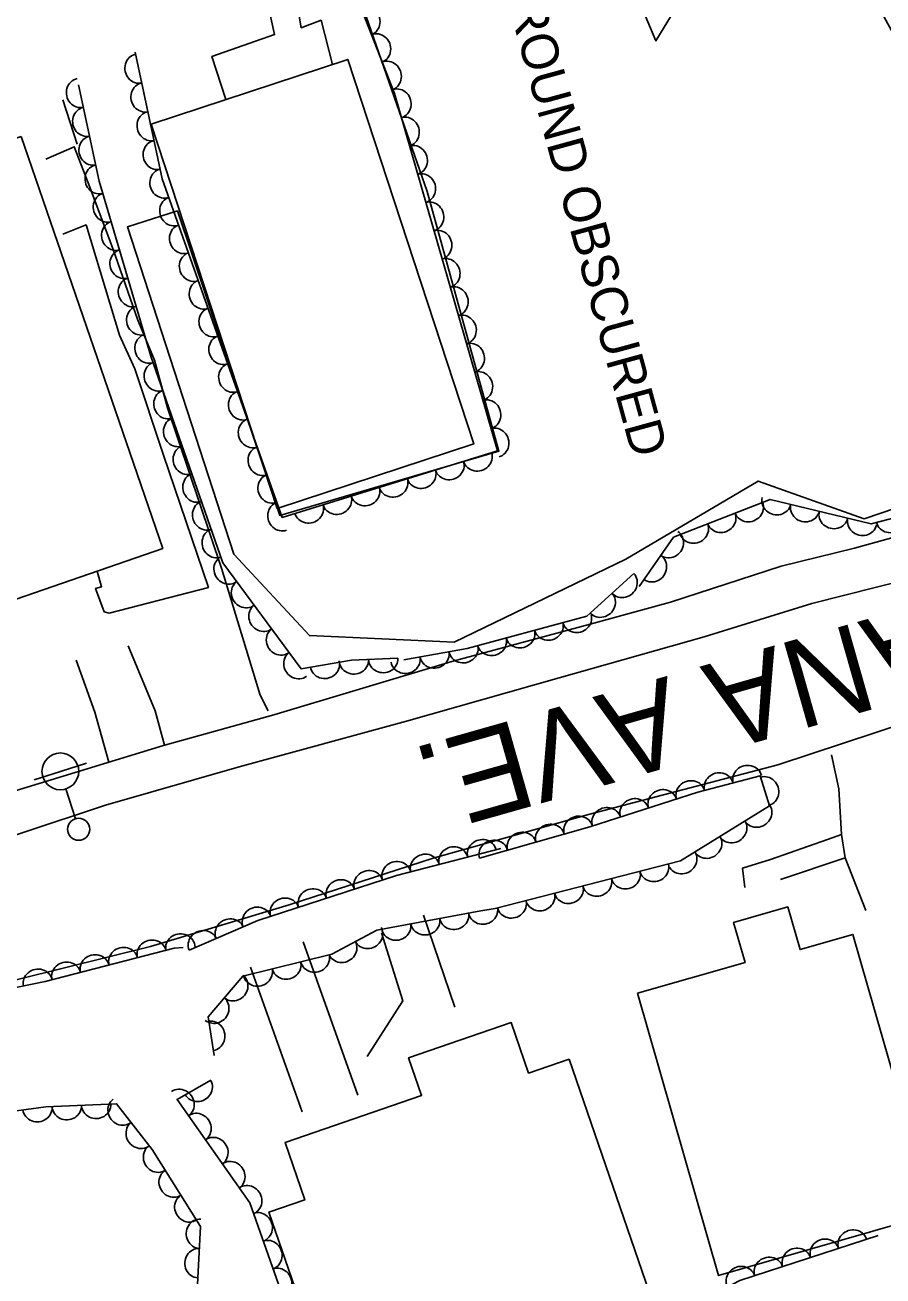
# Model space of a CAD drawing. Extents: x 1722896 to 1754269, y 648279 to 666297.
# Drawn here: x 1725232.8 to 1725349.5, y 665060.6 to 665230.7 of the extents above; entities that cross this region are included whole.
import ezdxf

# ---------------------------------------------------------------- set-up
doc = ezdxf.new("R2010")
doc.units = 0
for name, color, linetype in [('DESIGN - CENTERLINE - Proposed Text', 7, 'Continuous'), ('DESIGN - SHEET - Linework', 7, 'Continuous'), ('SURVEY - CENTERLINE - Preliminary', 7, 'Continuous'), ('SURVEY - CENTERLINE - Preliminary Text', 7, 'Continuous'), ('SURVEY - DTM - Breaklines', 7, 'Continuous'), ('SURVEY - VEGETATION - Features with Text', 7, 'Continuous')]:
    doc.layers.add(name, color=color, linetype=linetype)

msp = doc.modelspace()

# ---------------------------------------------------------------- linework, layer by layer
at = {"layer": 'DESIGN - CENTERLINE - Proposed Text'}
for points in [[(1725274.62, 665225.33), (1725273.06, 665231.34), (1725270.36, 665230.33), (1725269.07, 665237.77), (1725265.2, 665236.46), (1725266.72, 665229.4), (1725258.2, 665226.42), (1725260.12, 665220.57)], [(1725265.84, 665137.44), (1725264.75, 665139.58), (1725259.51, 665156.85), (1725252.15, 665178.66), (1725250.38, 665185.12), (1725248.14, 665190.57), (1725244.71, 665200.32), (1725241.39, 665209.23), (1725239.48, 665214.15), (1725235.62, 665212.47)], [(1725242.58, 665156.45), (1725243.2, 665154.31), (1725242.38, 665154.09), (1725243.57, 665150.91), (1725244.24, 665150.72), (1725257.73, 665154.23), (1725251.61, 665172.2), (1725247.7, 665183.94), (1725245.64, 665188.51), (1725241.08, 665203.52), (1725237.92, 665202.28)], [(1725245.64, 665157.48), (1725245.64, 665157.48)], [(1725330.68, 665113.43), (1725330.38, 665116.08), (1725334.17, 665117.24), (1725341.94, 665119.94), (1725343.84, 665120.62)], [(1725335.56, 665114.52), (1725344.35, 665117.47)], [(1725291.26, 665097.15), (1725286.97, 665109.66)], [(1725281.27, 665107.26), (1725284.18, 665098.02), (1725279.31, 665090.45)]]:
    msp.add_lwpolyline(points, dxfattribs=at)
for points in [[(1725249.93, 665217.23), (1725267.08, 665164.97), (1725293.83, 665173.75), (1725276.68, 665226.01)], [(1725232.24, 665215.53), (1725251.52, 665159.53), (1725224.05, 665150.07), (1725204.77, 665206.07)], [(1725316.1, 665099.05), (1725327.13, 665060.66), (1725356.32, 665069.05), (1725345.39, 665107.05), (1725338.2, 665104.99), (1725336.53, 665110.8), (1725329.16, 665108.68), (1725330.72, 665103.25)], [(1725306.79, 665090.09), (1725318.69, 665055.58), (1725275.79, 665040.8), (1725265.97, 665069.29), (1725270.84, 665070.96), (1725268.15, 665078.77), (1725286.72, 665085.17), (1725284.96, 665090.26), (1725298.92, 665095.07), (1725301.29, 665088.19)]]:
    msp.add_lwpolyline(points, close=True, dxfattribs=at)
at = {"layer": 'SURVEY - CENTERLINE - Preliminary'}
msp.add_lwpolyline([(1725301.17, 665269.92), (1725318.59, 665228.54), (1725330.19, 665247.6), (1725342.42, 665244.95), (1725356.56, 665219.19), (1725374.83, 665212.76), (1725380.19, 665187.77), (1725384.4, 665176.29), (1725346.92, 665163.57), (1725332.51, 665168.68), (1725314.53, 665158.06), (1725291.17, 665146.77), (1725271.47, 665147.68), (1725261.18, 665158.75), (1725246.72, 665203.25), (1725253.51, 665205.43), (1725267.43, 665164.03), (1725297.24, 665172.77), (1725287.5, 665208.06), (1725270.51, 665256.75), (1725301.17, 665269.92)], dxfattribs=at)
at = {"layer": 'SURVEY - CENTERLINE - Preliminary Text'}
for points in [[(1725519.42, 665223.67), (1725519.99, 665212.34), (1725515.67, 665197.19), (1725507.51, 665185.29), (1725492.83, 665177.77), (1725479.67, 665171.83), (1725461.36, 665165.41), (1725436.69, 665158.3), (1725416.91, 665154.11), (1725361.71, 665138.86), (1725335.17, 665130.12), (1725309.43, 665123.37), (1725288.3, 665117.43), (1725268.71, 665111.09), (1725249.84, 665105.41), (1725220, 665098.02), (1725197.01, 665091.34), (1725171.35, 665084.05), (1725152.36, 665078.27), (1725107.36, 665064.42), (1725081.37, 665056.76)], [(1725237.91, 665220.54), (1725239.88, 665214.51)], [(1725489.9, 665203.84), (1725487.04, 665201.88), (1725479.76, 665199.13), (1725463.22, 665193.38), (1725448.62, 665189.15), (1725429.03, 665183.37), (1725410.31, 665178.43), (1725386.01, 665171.28), (1725363.95, 665164.66), (1725345.61, 665159.57), (1725335.66, 665157.11), (1725320.58, 665152.24), (1725309.67, 665149.23), (1725290.83, 665144.14), (1725266.63, 665136.92), (1725251.62, 665132.76), (1725231.45, 665126.57)], [(1725488.25, 665195.87), (1725480.71, 665193.05), (1725469.88, 665189.35), (1725454.98, 665184.69), (1725439.96, 665180.41), (1725421.48, 665174.77), (1725402.66, 665169), (1725382, 665163.54), (1725357.22, 665156.45), (1725339.8, 665152.05), (1725325.18, 665147.53), (1725305.43, 665141.93), (1725284.68, 665136.03), (1725261.92, 665129.84), (1725243.74, 665124.63), (1725221.16, 665117.16)], [(1725251.77, 665132.8), (1725250.51, 665137.45), (1725246.8, 665146.28)], [(1725244.2, 665130.48), (1725242.27, 665137.29), (1725239.75, 665144.35)], [(1725342.47, 665131.47), (1725343.47, 665126.84), (1725343.84, 665120.62), (1725344.35, 665117.47), (1725347.15, 665110.29)], [(1725270.64, 665106.05), (1725278.07, 665085.2)], [(1725263.44, 665102.58), (1725270.5, 665082.92)]]:
    msp.add_lwpolyline(points, dxfattribs=at)
at = {"layer": 'SURVEY - DTM - Breaklines'}
for p, q in [((1725237.59, 665129.22), (1725241.17, 665130.35)), ((1725237.59, 665129.22), (1725234.02, 665128.09)), ((1725239.63, 665122.78), (1725238.35, 665126.83))]:
    msp.add_line(p, q, dxfattribs=at)
for centre, radius in [((1725237.59, 665129.22), 2.5), ((1725240.08, 665121.35), 1.5)]:
    msp.add_circle(centre, radius, dxfattribs=at)
at = {"layer": 'SURVEY - VEGETATION - Features with Text'}
for points in [[(1725307.02, 665265.01), (1725313.12, 665250.59), (1725318.35, 665236.46), (1725329.72, 665251.89), (1725344.39, 665249.29), (1725358.45, 665225.45), (1725377.49, 665216.11), (1725382.62, 665198.15), (1725383.22, 665187.56), (1725396.84, 665189.3), (1725402.66, 665186.31), (1725403.74, 665179.5), (1725390.43, 665174.92), (1725378.26, 665173.6), (1725361.33, 665166.37), (1725347.87, 665162.87), (1725334.14, 665166.18), (1725321.01, 665161.04), (1725316.32, 665154.34)], [(1725274.11, 665244.29), (1725283.02, 665221.4), (1725297.05, 665172.78), (1725267.76, 665163.74), (1725251.43, 665209.8), (1725247.78, 665227)], [(1725283.51, 665144.61), (1725277.21, 665144.32), (1725270.33, 665143.18), (1725259.69, 665157.58), (1725249.92, 665185.68), (1725242.89, 665209.46), (1725240.05, 665222.56)], [(1725315.61, 665156.12), (1725309.19, 665150.34), (1725292.93, 665145.94), (1725284.29, 665144.38)], [(1725294.59, 665117.42), (1725309.62, 665121.69), (1725324.3, 665126.39), (1725332.79, 665128.61), (1725334.04, 665124.55), (1725321.96, 665117.04), (1725296.73, 665110.58), (1725294.79, 665110.28), (1725280.62, 665107.64), (1725274.53, 665104.36), (1725262.39, 665101.39), (1725257.7, 665095.83), (1725258.51, 665090.6)], [(1725255.13, 665104.89), (1725264.47, 665108.93), (1725283.31, 665115.08), (1725297.5, 665118.72)], [(1725212.66, 665095.99), (1725235.53, 665100.65), (1725253.05, 665105.19), (1725254.28, 665105.26)], [(1725258.06, 665087.22), (1725253.47, 665084.63), (1725263.37, 665070.56), (1725268.66, 665055.5), (1725275.34, 665039.84), (1725293.87, 665046.03), (1725319.44, 665054.45), (1725330.02, 665059.98), (1725348.82, 665066.13)], [(1725256.21, 665058.59), (1725256.65, 665067.36), (1725250.06, 665077.83), (1725245.24, 665084.02), (1725235.6, 665083.6), (1725221.21, 665081.68)]]:
    msp.add_lwpolyline(points, dxfattribs=at)
for centre, major_axis in [((1725279.19, 665231.24), (0.73, -1.86)), ((1725280.64, 665227.52), (0.73, -1.86)), ((1725248.25, 665224.77), (-0.42, 1.96)), ((1725282.09, 665223.79), (0.73, -1.86)), ((1725240.29, 665221.45), (-0.42, 1.95)), ((1725249.08, 665220.86), (-0.42, 1.96)), ((1725283.42, 665220.02), (0.55, -1.92)), ((1725241.14, 665217.54), (-0.42, 1.95)), ((1725249.91, 665216.95), (-0.42, 1.96)), ((1725284.53, 665216.18), (0.55, -1.92)), ((1725241.99, 665213.63), (-0.42, 1.95)), ((1725250.74, 665213.03), (-0.42, 1.96)), ((1725285.64, 665212.33), (0.55, -1.92)), ((1725242.83, 665209.72), (-0.42, 1.95)), ((1725251.66, 665209.15), (-0.67, 1.89)), ((1725286.75, 665208.49), (0.55, -1.92)), ((1725243.95, 665205.88), (-0.57, 1.92)), ((1725253, 665205.37), (-0.67, 1.89)), ((1725287.86, 665204.65), (0.55, -1.92)), ((1725245.08, 665202.04), (-0.57, 1.92)), ((1725254.33, 665201.6), (-0.67, 1.89)), ((1725288.96, 665200.8), (0.55, -1.92)), ((1725246.22, 665198.21), (-0.57, 1.92)), ((1725255.67, 665197.83), (-0.67, 1.89)), ((1725290.07, 665196.96), (0.55, -1.92)), ((1725247.35, 665194.37), (-0.57, 1.92)), ((1725257.01, 665194.06), (-0.67, 1.89)), ((1725291.18, 665193.12), (0.55, -1.92)), ((1725248.48, 665190.53), (-0.57, 1.92)), ((1725258.34, 665190.29), (-0.67, 1.89)), ((1725292.29, 665189.27), (0.55, -1.92)), ((1725249.61, 665186.7), (-0.57, 1.92)), ((1725259.68, 665186.52), (-0.67, 1.89)), ((1725293.4, 665185.43), (0.55, -1.92)), ((1725250.88, 665182.91), (-0.66, 1.89)), ((1725261.02, 665182.75), (-0.67, 1.89)), ((1725294.51, 665181.59), (0.55, -1.92)), ((1725252.19, 665179.13), (-0.66, 1.89)), ((1725262.35, 665178.98), (-0.67, 1.89)), ((1725295.62, 665177.74), (0.55, -1.92)), ((1725253.51, 665175.35), (-0.66, 1.89)), ((1725263.69, 665175.21), (-0.67, 1.89)), ((1725296.72, 665173.9), (0.55, -1.92)), ((1725254.82, 665171.57), (-0.66, 1.89)), ((1725265.02, 665171.44), (-0.67, 1.89)), ((1725294.34, 665171.94), (-1.91, -0.59)), ((1725290.52, 665170.76), (-1.91, -0.59)), ((1725256.14, 665167.79), (-0.66, 1.89)), ((1725266.36, 665167.67), (-0.67, 1.89)), ((1725282.88, 665168.4), (-1.91, -0.59)), ((1725286.7, 665169.58), (-1.91, -0.59)), ((1725279.06, 665167.23), (-1.91, -0.59)), ((1725257.45, 665164.02), (-0.66, 1.89)), ((1725267.7, 665163.9), (-0.67, 1.89)), ((1725271.41, 665164.87), (-1.91, -0.59)), ((1725275.23, 665166.05), (-1.91, -0.59)), ((1725331.24, 665165.04), (-1.86, -0.73)), ((1725335, 665165.97), (-1.94, 0.47)), ((1725338.89, 665165.03), (-1.94, 0.47)), ((1725327.51, 665163.59), (-1.86, -0.73)), ((1725342.77, 665164.1), (-1.94, 0.47)), ((1725346.66, 665163.16), (-1.94, 0.47)), ((1725350.54, 665163.56), (-1.94, -0.5)), ((1725258.76, 665160.24), (-0.66, 1.89)), ((1725320.43, 665160.21), (-1.15, -1.64)), ((1725323.79, 665162.13), (-1.86, -0.73)), ((1725318.14, 665156.93), (-1.15, -1.64)), ((1725260.4, 665156.63), (-1.19, 1.61)), ((1725314.12, 665154.78), (-1.49, -1.34)), ((1725262.77, 665153.41), (-1.19, 1.61)), ((1725311.15, 665152.1), (-1.49, -1.34)), ((1725265.15, 665150.19), (-1.19, 1.61)), ((1725307.87, 665149.98), (-1.93, -0.52)), ((1725267.53, 665146.98), (-1.19, 1.61)), ((1725300.15, 665147.89), (-1.93, -0.52)), ((1725304.01, 665148.94), (-1.93, -0.52)), ((1725296.29, 665146.85), (-1.93, -0.52)), ((1725269.9, 665143.76), (-1.19, 1.61)), ((1725288.48, 665145.14), (-1.97, -0.36)), ((1725292.42, 665145.85), (-1.97, -0.36)), ((1725273.57, 665143.72), (-1.97, -0.33)), ((1725277.52, 665144.33), (-2, -0.09)), ((1725281.51, 665144.52), (-2, -0.09)), ((1725284.55, 665144.42), (-1.97, -0.36)), ((1725331.03, 665128.15), (1.93, 0.51)), ((1725323.31, 665126.07), (1.9, 0.61)), ((1725327.16, 665127.14), (1.93, 0.51)), ((1725333.43, 665126.52), (0.59, -1.91)), ((1725319.5, 665124.85), (1.9, 0.61)), ((1725311.88, 665122.41), (1.9, 0.61)), ((1725315.69, 665123.63), (1.9, 0.61)), ((1725332.4, 665123.53), (-1.7, -1.06)), ((1725308.05, 665121.25), (1.92, 0.55)), ((1725300.36, 665119.06), (1.92, 0.55)), ((1725304.21, 665120.15), (1.92, 0.55)), ((1725329, 665121.42), (-1.7, -1.06)), ((1725294.94, 665118.06), (1.94, 0.5)), ((1725296.51, 665117.97), (1.92, 0.55)), ((1725325.6, 665119.31), (-1.7, -1.06)), ((1725287.19, 665116.07), (1.94, 0.5)), ((1725291.06, 665117.07), (1.94, 0.5)), ((1725322.2, 665117.2), (-1.7, -1.06)), ((1725279.51, 665113.84), (1.9, 0.62)), ((1725283.31, 665115.08), (1.9, 0.62)), ((1725318.36, 665116.12), (-1.94, -0.5)), ((1725275.71, 665112.6), (1.9, 0.62)), ((1725310.61, 665114.14), (-1.94, -0.5)), ((1725314.49, 665115.13), (-1.94, -0.5)), ((1725271.9, 665111.36), (1.9, 0.62)), ((1725302.86, 665112.15), (-1.94, -0.5)), ((1725306.74, 665113.15), (-1.94, -0.5)), ((1725264.31, 665108.86), (1.84, 0.79)), ((1725268.1, 665110.11), (1.9, 0.62)), ((1725298.99, 665111.16), (-1.94, -0.5)), ((1725260.63, 665107.27), (1.84, 0.79)), ((1725287.22, 665108.87), (-1.97, -0.37)), ((1725291.15, 665109.6), (-1.97, -0.37)), ((1725295.08, 665110.32), (-1.98, -0.31)), ((1725256.96, 665105.68), (1.84, 0.79)), ((1725279.48, 665107.03), (-1.76, -0.95)), ((1725283.28, 665108.14), (-1.97, -0.37)), ((1725250.02, 665104.4), (1.94, 0.5)), ((1725253.92, 665105.24), (2, 0.12)), ((1725275.96, 665105.14), (-1.76, -0.95)), ((1725242.27, 665102.4), (1.94, 0.5)), ((1725246.15, 665103.4), (1.94, 0.5)), ((1725272.22, 665103.8), (-1.94, -0.48)), ((1725234.52, 665100.45), (1.96, 0.4)), ((1725238.4, 665101.4), (1.94, 0.5)), ((1725264.45, 665101.9), (-1.94, -0.48)), ((1725268.34, 665102.85), (-1.94, -0.48)), ((1725261.18, 665099.96), (-1.29, -1.53)), ((1725258.6, 665096.9), (-1.29, -1.53)), ((1725258.09, 665093.26), (0.31, -1.98)), ((1725256.32, 665086.23), (-1.74, -0.98)), ((1725253.88, 665084.04), (1.15, -1.64)), ((1725234.48, 665083.45), (-1.98, -0.26)), ((1725238.47, 665083.72), (-2, -0.09)), ((1725242.46, 665083.9), (-2, -0.09)), ((1725245.99, 665083.06), (-1.23, 1.58)), ((1725256.18, 665080.77), (1.15, -1.64)), ((1725248.45, 665079.9), (-1.23, 1.58)), ((1725258.49, 665077.5), (1.15, -1.64)), ((1725250.79, 665076.66), (-1.07, 1.69)), ((1725260.79, 665074.23), (1.15, -1.64)), ((1725252.92, 665073.28), (-1.07, 1.69)), ((1725263.09, 665070.95), (1.15, -1.64)), ((1725255.05, 665069.9), (-1.07, 1.69)), ((1725256.6, 665066.36), (0.1, 2)), ((1725264.54, 665067.24), (0.66, -1.89)), ((1725345.35, 665064.99), (1.9, 0.62)), ((1725265.86, 665063.47), (0.66, -1.89)), ((1725341.55, 665063.75), (1.9, 0.62)), ((1725256.4, 665062.36), (0.1, 2)), ((1725333.94, 665061.27), (1.9, 0.62)), ((1725337.74, 665062.51), (1.9, 0.62)), ((1725267.18, 665059.69), (0.66, -1.89)), ((1725330.14, 665060.03), (1.9, 0.62))]:
    msp.add_ellipse(centre, major_axis=major_axis, ratio=0.940188, start_param=0, end_param=3.141593, dxfattribs=at)

# ---------------------------------------------------------------- texts
at = {"layer": 'DESIGN - SHEET - Linework'}
msp.add_text('INDIANA AVE.', height=12, rotation=195.8476, dxfattribs=at).set_placement((1725387.1, 665161.21))
at = {"layer": 'SURVEY - CENTERLINE - Preliminary'}
msp.add_text('GROUND OBSCURED', height=5, rotation=285.3494, dxfattribs=at).set_placement((1725297.1, 665238.59))

doc.saveas('drawing.dxf')
